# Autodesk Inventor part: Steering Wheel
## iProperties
Shininess: 77.0
Angle Display Precision: 2
Document Length Units: 11269
Document Angle Units: 11279
Document Time Units: 11290
Document Mass Units: 11283
Document Length Units Precision: 3
Document Angle Units Precision: 2
Compacted: True
Created: 2001-08
Part Number: Steering Wheel
Document SubType Name: Sheet Metal
Designer: Martin Budgell
Density: 0.0
Volumn: 0.0
Area: 0.0
PropertySet Name: Model Information
Control State: 0
Master: False
Checked Out: False
Author: Martin Budgell
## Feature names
1. Extrusion1
2. Circular Pattern1
3. Circular Pattern2
4. Chamfer1
5. Hole1
6. Circular Pattern3
7. Extrusion2
8. Circular Pattern4
9. Revolution1
10. Fillet1
11. Plate1
12. Cut1
